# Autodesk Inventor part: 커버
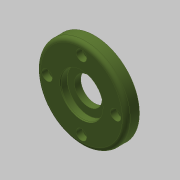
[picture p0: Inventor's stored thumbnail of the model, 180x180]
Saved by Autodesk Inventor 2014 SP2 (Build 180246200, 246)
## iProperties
Created: 2016-06
Part Number: 커버
Material: 알루미늄 6061
Document SubType Name: Modeling
Designer: mduedu
Density: 2.71 g/cm^3
Appearance: 올리브 녹색
Author: mduedu
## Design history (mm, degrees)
sketch "스케치1"
  geometry: C1 r 34 at (0, 0); 1 further point
  constraints: 1 centre point, 1 coincident
  dimensions: "d0" = 68 diameter of C1
extrude "돌출1" new body sketch "스케치1" distance "d2" = 10; taper "d3" = 0 deg
sketch "스케치2"
  geometry: C1 r 21 at (0, 0); 1 further point
  constraints: 1 centre point, 1 coincident
  dimensions: "d4" = 42 diameter of C1
extrude "돌출2" join sketch "스케치2" distance "d6" = 3; taper "d7" = 0 deg
fillet "모깎기1" dims "d8" = 3
hole "구멍1" diameter "d11" = 35; stored, may be unused: countersink angle "d15" = 90 deg, drill point angle "d17" = 0 deg; dims "d9" = 10, "d10" = 10, "d12" = 6, "d13" = 4, "d14" = 2, "d16" = 3
hole "구멍2" diameter "d20" = 32; stored, may be unused: countersink angle "d24" = 90 deg, drill point angle "d26" = 0 deg; dims "d21" = 6, "d22" = 4, "d23" = 2, "d25" = 5.2, "d46" = 10, "d47" = 10
hole "구멍3" diameter "d29" = 21; stored, may be unused: countersink angle "d33" = 90 deg, drill point angle "d35" = 0 deg; dims "d27" = 10, "d28" = 10, "d30" = 6, "d31" = 4, "d32" = 2, "d34" = 5
fillet "모깎기2" dims "d36" = 3
fillet "모깎기3" dims "d37" = 0.1
chamfer "모따기1" distance "d38" = 0.75; stored, may be unused: second distance "d39" = 2, angle "d40" = 30 deg
chamfer "모따기2" distance "d42" = 0.5; stored, may be unused: second distance "d43" = 2, angle "d44" = 30 deg
sketch "스케치3" dims "d48" = 52
  geometry: 6 further points
  constraints: 2 vertical alignment, 1 coincident, 7 other
  dimensions: "d51" = 360 deg dimension on point (0, 0) point (0, 26) (derived)
sketch "스케치4"
  geometry: 4 further points
hole "구멍4" sketch "스케치4" at (0, 26), (-26, 0), (0, -26), (26, 0) diameter "d53" = 4.5; stored, may be unused: countersink angle "d57" = 90 deg, drill point angle "d59" = 0 deg; dims "d54" = 6, "d55" = 8, "d56" = 4.6, "d58" = 8
node "솔리드1"
